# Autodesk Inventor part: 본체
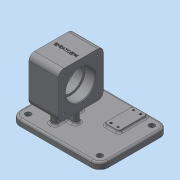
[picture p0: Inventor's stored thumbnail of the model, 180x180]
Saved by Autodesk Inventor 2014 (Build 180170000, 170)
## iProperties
Created: 2019-09
Part Number: 본체
Material: 알루미늄 6061
Document SubType Name: Modeling
Designer: mduedu
Density: 2.71 g/cm^3
Appearance: 기본값
Mass: 636.364 g
Surface Area: 520.125 cm^2
Volume: 234.821 cm^3
Author: mduedu
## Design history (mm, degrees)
sketch "스케치1"
  geometry: L1 (42, -62)-(-84, -62); L2 (-84, -62)-(-84, 36); L3 (-84, 36)-(42, 36); L4 (42, 36)-(42, -62); 1 further point
  constraints: 8 end point, 2 parallel, 1 horizontal, 1 perpendicular
  dimensions: "d0" = 36 distance from line of L3 point (0, 0); "d1" = 98 distance of L1.end L2.end; "d2" = 42 distance from line of L4 point (0, 0); "d3" = 126 distance of L2.end L3.end
extrude "돌출1" new body sketch "스케치1" distance "d4" = 9; taper "d5" = 0 deg
sketch "스케치2"
  geometry: L1 (0, -62)-(0, 36) reference; L2 (27, -32)-(91, -32); L3 (91, -32)-(91, 32); L4 (91, 32)-(27, 32); L5 (27, 32)-(27, -32); L6 (27, -32)-(91, 32); L7 (91, -32)-(27, 32); 3 further points
  constraints: 12 end point, 3 midpoint, 2 parallel, 1 horizontal, 1 horizontal alignment, 1 perpendicular
  dimensions: "d87" = 64 distance of L4.end L3.end; "d88" = 64 distance of L3.end L2.end; "d89" = 59 distance from line of point (59, 0) L1
extrude "돌출2" join sketch "스케치2" stored distance "d8" = 42; taper "d9" = 0 deg
sketch "스케치3"
  geometry: L1 (-17, 4)-(17, 4); L2 (17, 4)-(17, -4); L3 (17, -4)-(-17, -4); L4 (-17, -4)-(-17, 4); L5 (-4, 20)-(4, 20); L6 (4, 20)-(4, -20); L7 (4, -20)-(-4, -20); L8 (-4, -20)-(-4, 20); 5 further points
  constraints: 16 end point, 4 midpoint, 4 parallel, 2 horizontal, 2 horizontal alignment, 2 perpendicular, 2 vertical alignment
  dimensions: "d10" = 8 distance of L5.start L5.end; "d12" = 8 distance of L1.end L2.end; "d13" = 34 distance of L2.end L3.end; "d14" = 40 distance of L5.end L6.end
extrude "돌출3" join sketch "스케치3" stored distance "d15" = 42; taper "d16" = 0 deg
sketch "스케치4"
  geometry: L1 (-32, 91)-(-32, 27) reference; L2 (32, 91)-(-32, 91) reference; L3 (32, 27)-(32, 91) reference; L4 (-32, 27)-(32, 27) reference; C1 r 21 at (0, 59); 3 further points
  constraints: 2 midpoint, 1 centre point, 1 horizontal alignment, 1 vertical alignment
  dimensions: "d17" = 42 diameter of C1
extrude "돌출4" cut sketch "스케치4" distance "d18" = 15; taper "d19" = 0 deg
hole "구멍1" diameter "d22" = 36; stored, may be unused: countersink angle "d26" = 90 deg, drill point angle "d28" = 118 deg; dims "d20" = 10, "d21" = 10, "d23" = 6, "d24" = 4, "d25" = 2, "d27" = 8
fillet "모깎기1" dims "d29" = 0.3
chamfer "모따기1" distance "d30" = 1; stored, may be unused: second distance "d31" = 2, angle "d32" = 45 deg
fillet "모깎기9" dims "d90" = 8
sketch "스케치11"
  geometry: L1 (-24, 27)-(24, 27) reference; L2 (32, 35)-(32, 83) reference; L3 (24, 91)-(-24, 91) reference; L4 (-32, 83)-(-32, 35) reference; C1 r 22 at (0, 59) reference; A1 r 8 centre (-24, 35) between (-32, 35) and (-24, 27) reference; A2 r 8 centre (24, 35) between (24, 27) and (32, 35) reference; A3 r 8 centre (24, 83) between (32, 83) and (24, 91) reference; A4 r 8 centre (-24, 83) between (-24, 91) and (-32, 83) reference; 5 further points
  constraints: 4 coincident
hole "구멍6" sketch "스케치11" at (-24, 83), (24, 83), (24, 35), (-24, 35) diameter "d91" = 3.242; stored, may be unused: countersink angle "d95" = 90 deg, drill point angle "d97" = 118 deg; dims "d92" = 8, "d93" = 4, "d94" = 2, "d96" = 10
fillet "모깎기2" dims "d44" = 12
sketch "스케치6"
  geometry: L1 (-42, 50)-(-42, -24) reference; L2 (-30, -36)-(72, -36) reference; L3 (84, -24)-(84, 50) reference; L4 (72, 62)-(-30, 62) reference; L5 (17, 4)-(17, -4) reference; L6 (17, -4)-(4, -4) reference; L7 (4, -4)-(4, -20) reference; L8 (4, -20)-(-4, -20) reference; L9 (-4, -20)-(-4, -4) reference; L10 (-4, -4)-(-17, -4) reference; L11 (-17, -4)-(-17, 4) reference; L12 (-17, 4)-(-4, 4) reference; L13 (-4, 4)-(-4, 20) reference; L14 (-4, 20)-(4, 20) reference; L15 (4, 20)-(4, 4) reference; L16 (4, 4)-(17, 4) reference; A1 r 12 centre (-30, 50) between (-30, 62) and (-42, 50) reference; A2 r 12 centre (-30, -24) between (-42, -24) and (-30, -36) reference; A3 r 12 centre (72, -24) between (72, -36) and (84, -24) reference; A4 r 12 centre (72, 50) between (84, 50) and (72, 62) reference; 5 further points
  constraints: 4 coincident
hole "구멍3" sketch "스케치6" at (-30, 50), (72, 50), (72, -24), (-30, -24) diameter "d45" = 8; stored, may be unused: countersink angle "d49" = 90 deg, drill point angle "d51" = 118 deg; dims "d46" = 8, "d47" = 4, "d48" = 2, "d50" = 10
sketch "스케치7"
  geometry: L1 (38, 57)-(58, 57); L2 (58, 57)-(58, 17); L3 (58, 17)-(38, 17); L4 (38, 17)-(38, 57); L5 (72, 62)-(-30, 62) reference; 3 further points
  constraints: 8 end point, 2 midpoint, 2 parallel, 1 horizontal, 1 perpendicular
  dimensions: "d52" = 48 horizontal distance of point (48, 57) point (0, 0); "d53" = 20 distance of L1.start L1.end; "d54" = 40 distance of L1.end L2.end; "d55" = 25 distance from line of point (38, 37) L5
extrude "돌출5" join sketch "스케치7" distance "d56" = 3; taper "d57" = 0 deg
fillet "모깎기3" dims "d58" = 3
fillet "모깎기4" dims "d59" = 3
fillet "모깎기5" dims "d60" = 3
fillet "모깎기6" dims "d61" = 3
fillet "모깎기7" dims "d62" = 3
fillet "모깎기8" dims "d63" = 3
sketch "스케치8"
  geometry: L1 (72, 62)-(58.317, 62) reference; L2 (84, -24)-(84, 50) reference; C1 r 1.5 at (43, 53); C2 r 1.5 at (53, 21); 1 further point
  constraints: 2 centre point, 1 equal radius
  dimensions: "d64" = 3 diameter of C1; "d65" = 9 distance from line of C1.centre L1; "d66" = 32 vertical distance of C2.centre C1.centre; "d67" = 10 horizontal distance of C2.centre C1.centre; "d68" = 31 distance from line of L2 C2.centre
hole "구멍4" sketch "스케치8" at (43, 53), (53, 21) diameter "d69" = 3; stored, may be unused: countersink angle "d73" = 90 deg, drill point angle "d75" = 118 deg; dims "d70" = 8, "d71" = 4, "d72" = 2, "d74" = 6
sketch "스케치9"
  geometry: C1 r 1.5 at (43, 53) reference; C2 r 1.5 at (53, 21) reference; 3 further points
  constraints: 2 horizontal alignment, 2 vertical alignment
hole "구멍5" sketch "스케치9" at (53, 53), (43, 21) diameter "d76" = 3.242; stored, may be unused: countersink angle "d80" = 90 deg, drill point angle "d82" = 118 deg; dims "d77" = 6, "d78" = 4, "d79" = 2, "d81" = 8
sketch "스케치10"
  geometry: 2 further points
  constraints: 1 coincident, 1 other
feature "엠보싱1" sketch "스케치10" dims "d0" = 36, "d1" = 98, "d2" = 42, "d3" = 126, "d12" = 8, "d13" = 34, "d85" = 0.5, "d86" = 0
node "솔리드1"
mirror "대칭1"
mirror "대칭2"
node "투영된 루프1"
node "투영된 루프2"
